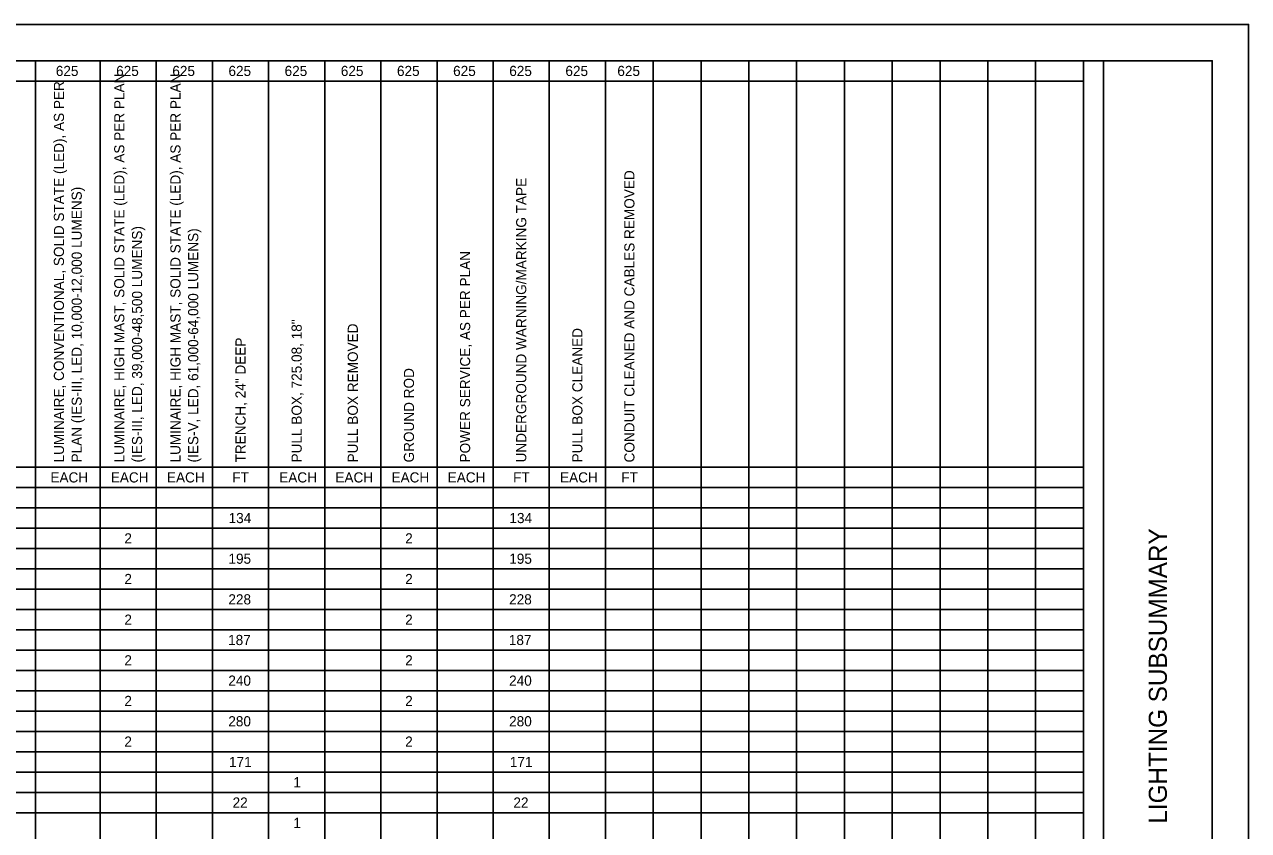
# Model space of a CAD drawing. Extents: x 0 to 34, y 0 to 22.
# Drawn here: x 17.13 to 34, y 10.89 to 22 of the extents above; entities that cross this region are included whole.
import ezdxf

# ---------------------------------------------------------------- set-up
doc = ezdxf.new("R2010")
doc.units = 0
for name, color, linetype in [('Default', 7, 'Continuous'), ('SH_Border', 7, 'Continuous'), ('SH_Cut_Line', 7, 'Continuous'), ('SH_Data', 7, 'Continuous')]:
    doc.layers.add(name, color=color, linetype=linetype)

msp = doc.modelspace()

# ---------------------------------------------------------------- linework, layer by layer
at = {"layer": 'Default'}
for p, q in [((1.5, 21.5), (31.724, 21.5)), ((17.279, 21.5), (17.279, 0.5)), ((18.168, 21.5), (18.168, 0.5)), ((18.942, 21.5), (18.942, 0.5)), ((19.716, 21.5), (19.716, 0.5)), ((20.491, 21.5), (20.491, 0.5)), ((21.265, 21.5), (21.265, 0.5)), ((22.039, 21.5), (22.039, 0.5)), ((22.813, 21.5), (22.813, 0.5)), ((23.587, 21.5), (23.587, 0.5)), ((24.361, 21.5), (24.361, 0.5)), ((25.135, 21.5), (25.135, 0.5)), ((25.794, 21.5), (25.794, 0.5)), ((26.453, 21.5), (26.453, 0.5)), ((27.112, 21.5), (27.112, 0.5)), ((27.771, 21.5), (27.771, 0.5)), ((28.429, 21.5), (28.429, 0.5)), ((29.088, 21.5), (29.088, 0.5)), ((29.747, 21.5), (29.747, 0.5)), ((30.406, 21.5), (30.406, 0.5)), ((31.065, 21.5), (31.065, 0.5)), ((31.724, 21.5), (31.724, 0.5)), ((8.451, 21.22), (31.724, 21.22)), ((8.451, 15.9), (31.724, 15.9)), ((1.5, 15.62), (31.724, 15.62)), ((1.5, 15.34), (31.724, 15.34)), ((1.5, 15.06), (31.724, 15.06)), ((1.5, 14.78), (31.724, 14.78)), ((1.5, 14.5), (31.724, 14.5)), ((1.5, 14.22), (31.724, 14.22)), ((1.5, 13.94), (31.724, 13.94)), ((1.5, 13.66), (31.724, 13.66)), ((1.5, 13.38), (31.724, 13.38)), ((1.5, 13.1), (31.724, 13.1)), ((1.5, 12.82), (31.724, 12.82)), ((1.5, 12.54), (31.724, 12.54)), ((1.5, 12.26), (31.724, 12.26)), ((1.5, 11.98), (31.724, 11.98)), ((1.5, 11.7), (31.724, 11.7)), ((1.5, 11.42), (31.724, 11.42)), ((1.5, 11.14), (31.724, 11.14))]:
    msp.add_line(p, q, dxfattribs=at)
at = {"layer": 'SH_Border'}
msp.add_line((32, 0.5), (32, 21.5), dxfattribs=at)
msp.add_lwpolyline([(1.5, 21.5), (33.5, 21.5), (33.5, 0.5), (1.5, 0.5)], close=True, dxfattribs=at)
at = {"layer": 'SH_Cut_Line'}
msp.add_lwpolyline([(0, 0), (34, 0), (34, 22), (0, 22)], close=True, dxfattribs=at)

# ---------------------------------------------------------------- texts
at = {"layer": 'Default'}
for s, p in [('625', (17.558, 21.29)), ('625', (18.39, 21.29)), ('625', (19.164, 21.29)), ('625', (19.938, 21.29)), ('625', (20.712, 21.29)), ('625', (21.487, 21.29)), ('625', (22.261, 21.29)), ('625', (23.035, 21.29)), ('625', (23.809, 21.29)), ('625', (24.583, 21.29)), ('625', (25.299, 21.29)), ('EACH', (17.484, 15.69)), ('EACH', (18.316, 15.69)), ('EACH', (19.09, 15.69)), ('FT', (19.991, 15.69)), ('EACH', (20.638, 15.69)), ('EACH', (21.412, 15.69)), ('EACH', (22.186, 15.69)), ('EACH', (22.96, 15.69)), ('FT', (23.862, 15.69)), ('EACH', (24.509, 15.69)), ('FT', (25.353, 15.69)), ('134', (19.94, 15.13)), ('134', (23.811, 15.13)), ('2', (18.503, 14.85)), ('2', (22.374, 14.85)), ('195', (19.938, 14.57)), ('195', (23.809, 14.57)), ('2', (18.503, 14.29)), ('2', (22.374, 14.29)), ('228', (19.937, 14.01)), ('228', (23.807, 14.01)), ('2', (18.503, 13.73)), ('2', (22.374, 13.73)), ('187', (19.933, 13.45)), ('187', (23.803, 13.45)), ('2', (18.503, 13.17)), ('2', (22.374, 13.17)), ('240', (19.936, 12.89)), ('240', (23.807, 12.89)), ('2', (18.503, 12.61)), ('2', (22.374, 12.61)), ('280', (19.936, 12.33)), ('280', (23.807, 12.33)), ('2', (18.503, 12.05)), ('2', (22.374, 12.05)), ('171', (19.946, 11.77)), ('171', (23.817, 11.77)), ('1', (20.832, 11.49)), ('22', (19.995, 11.21)), ('22', (23.866, 11.21)), ('1', (20.832, 10.93))]:
    msp.add_text(s, height=0.14, dxfattribs=at).set_placement(p)
for s, p in [('LUMINAIRE, HIGH MAST, SOLID STATE (LED), AS PER PLAN ', (18.503, 15.966)), ('LUMINAIRE, HIGH MAST, SOLID STATE (LED), AS PER PLAN ', (19.277, 15.966)), ('LUMINAIRE, CONVENTIONAL, SOLID STATE (LED), AS PER ', (17.671, 15.966)), ('CONDUIT CLEANED AND CABLES REMOVED', (25.535, 15.966)), ('PLAN (IES-III, LED, 10,000-12,000 LUMENS)', (17.916, 15.966)), ('UNDERGROUND WARNING/MARKING TAPE', (24.044, 15.966)), ('(IES-III, LED, 39,000-48,500 LUMENS)', (18.748, 15.966)), ('(IES-V, LED, 61,000-64,000 LUMENS)', (19.522, 15.966)), ('POWER SERVICE, AS PER PLAN', (23.27, 15.966)), ('PULL BOX, 725.08, 18"', (20.948, 15.966)), ('PULL BOX REMOVED', (21.722, 15.966)), ('PULL BOX CLEANED', (24.818, 15.966)), ('TRENCH, 24" DEEP', (20.174, 15.966)), ('GROUND ROD', (22.496, 15.966))]:
    msp.add_text(s, height=0.14, rotation=90, dxfattribs=at).set_placement(p)
at = {"layer": 'SH_Data'}
msp.add_text('LIGHTING SUBSUMMARY', height=0.25, rotation=90, dxfattribs=at).set_placement((32.875, 10.99))

doc.saveas('drawing.dxf')
